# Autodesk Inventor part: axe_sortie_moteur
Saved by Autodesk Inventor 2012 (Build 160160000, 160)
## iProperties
Created: 2013-08
Part Number: axe_sortie_moteur
Material: Default
Document SubType Name: Modeling
Designer: hilarion
Density: 1 g/cm^3
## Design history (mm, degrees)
node "axe_sortie_moteur1"
node "axe_sortie_moteur"
node "Base1"
